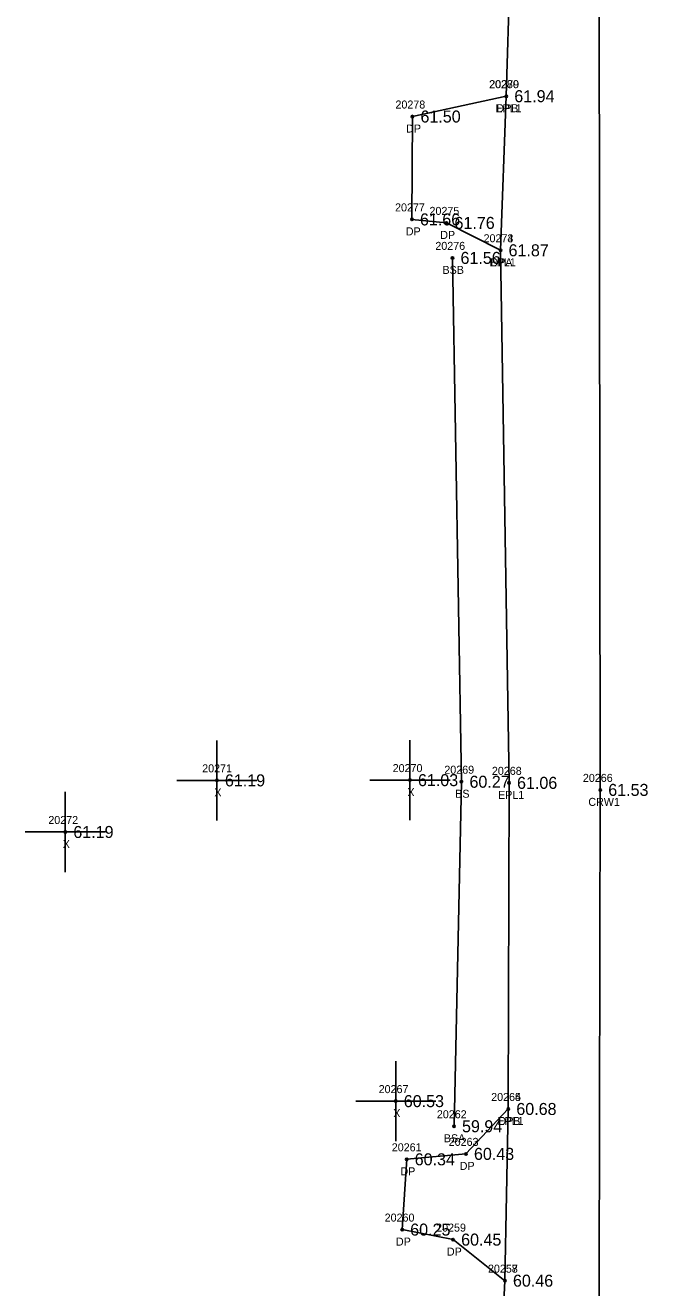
# Model space of a CAD drawing. Extents: x 2420351 to 2422725, y 845330 to 846558.
# Drawn here: x 2420888.2 to 2420966, y 845834.4 to 845992.1 of the extents above; entities that cross this region are included whole.
import ezdxf

# ---------------------------------------------------------------- set-up
doc = ezdxf.new("R2010")
doc.units = 0
for name, color, linetype in [('RD_DTM_BkLn1', 7, 'Continuous'), ('RD_DTM_BkLn2', 7, 'Continuous'), ('RD_DTM_BkLn_txCode', 7, 'Continuous'), ('RD_EX_Driveway', 7, 'Continuous'), ('RD_EX_Driveway_txCode', 7, 'Continuous'), ('RD_EX_Misc', 7, 'Continuous'), ('RD_EX_Misc_txCode', 7, 'Continuous'), ('RD_EX_Road', 7, 'Continuous'), ('RD_EX_Road_txCode', 7, 'Continuous'), ('RD_EX_TX_Driveway_ELEV', 7, 'Continuous'), ('RD_EX_TX_Misc_ELEV', 7, 'Continuous'), ('RD_EX_TX_Road_ELEV', 7, 'Continuous'), ('RD_HC_Survey_ELEV', 7, 'Continuous'), ('RD_HC_Survey_txCode', 7, 'Continuous'), ('RD_SMD_Locator', 7, 'Continuous')]:
    doc.layers.add(name, color=color, linetype=linetype)

msp = doc.modelspace()

# ---------------------------------------------------------------- linework, layer by layer
at = {"layer": 'RD_DTM_BkLn1'}
msp.add_lwpolyline([(2420953.84, 845715.4), (2420955.91, 845728.49), (2420958.05, 845746.39), (2420959.33, 845767.92), (2420959.83, 845794.17), (2420960.04, 845896.62), (2420959.9, 845997.98), (2420960.79, 846105.06), (2420961.13, 846198.92)], dxfattribs=at)
at = {"layer": 'RD_DTM_BkLn2'}
msp.add_lwpolyline([(2420941.78, 845854.6), (2420942.71, 845897.64), (2420941.59, 845963.08)], dxfattribs=at)
at = {"layer": 'RD_EX_Driveway'}
for points in [[(2420947.59, 845964.03), (2420940.84, 845967.45), (2420936.53, 845967.89), (2420936.59, 845980.74), (2420948.31, 845983.28)], [(2420948.14, 845835.31), (2420941.67, 845840.44), (2420935.31, 845841.69), (2420935.87, 845850.47), (2420943.27, 845851.15), (2420948.56, 845856.76)]]:
    msp.add_lwpolyline(points, dxfattribs=at)
at = {"layer": 'RD_EX_Misc'}
for p, q in [((2420912.18, 845892.81), (2420912.18, 845902.81)), ((2420936.28, 845892.84), (2420936.28, 845902.84)), ((2420907.18, 845897.81), (2420917.18, 845897.81)), ((2420931.28, 845897.84), (2420941.28, 845897.84)), ((2420893.25, 845886.36), (2420893.25, 845896.36)), ((2420888.25, 845891.36), (2420898.25, 845891.36)), ((2420934.51, 845852.74), (2420934.51, 845862.74)), ((2420929.51, 845857.74), (2420939.51, 845857.74))]:
    msp.add_line(p, q, dxfattribs=at)
at = {"layer": 'RD_EX_Road'}
msp.add_lwpolyline([(2420911.08, 845716.87), (2420926.22, 845723.04), (2420936.01, 845731.06), (2420942.67, 845742.11), (2420946.54, 845756.04), (2420945.56, 845775.49), (2420946.2, 845794.55), (2420948.14, 845835.31), (2420948.56, 845856.76), (2420948.65, 845897.5), (2420947.59, 845964.03), (2420948.31, 845983.28), (2420948.75, 845998.25), (2420949.7, 846105.56), (2420949.53, 846120.86), (2420949.28, 846141.3), (2420949.41, 846199.43)], dxfattribs=at)
at = {"layer": 'RD_SMD_Locator'}
for centre in [(2420948.31, 845983.28), (2420948.31, 845983.28), (2420936.59, 845980.74), (2420936.53, 845967.89), (2420940.84, 845967.45), (2420947.59, 845964.03), (2420947.59, 845964.03), (2420941.59, 845963.08), (2420912.18, 845897.81), (2420936.28, 845897.84), (2420942.71, 845897.64), (2420948.65, 845897.5), (2420960.04, 845896.62), (2420893.25, 845891.36), (2420934.51, 845857.74), (2420948.56, 845856.76), (2420948.56, 845856.76), (2420941.78, 845854.6), (2420935.87, 845850.47), (2420943.27, 845851.15), (2420935.31, 845841.69), (2420941.67, 845840.44), (2420948.14, 845835.31), (2420948.14, 845835.31)]:
    msp.add_circle(centre, 0.15, dxfattribs=at)

# ---------------------------------------------------------------- texts
at = {"layer": 'RD_DTM_BkLn_txCode'}
for s, p in [('20276', (2420939.45, 845964.08)), ('BSB', (2420940.34, 845961.08)), ('20269', (2420940.57, 845898.64)), ('BS', (2420941.93, 845895.64)), ('20262', (2420939.64, 845855.6)), ('BSA', (2420940.51, 845852.6))]:
    msp.add_text(s, height=1, dxfattribs=at).set_placement(p)
at = {"layer": 'RD_EX_Driveway_txCode'}
for s, p in [('20279', (2420946.19, 845984.28)), ('20278', (2420934.47, 845981.74)), ('DPB', (2420947.06, 845981.28)), ('DP', (2420935.81, 845978.74)), ('20277', (2420934.42, 845968.89)), ('20275', (2420938.72, 845968.45)), ('DP', (2420935.76, 845965.89)), ('DP', (2420940.06, 845965.45)), ('20274', (2420945.47, 845965.03)), ('DPA', (2420946.32, 845962.03)), ('20264', (2420946.42, 845857.76)), ('DPB', (2420947.31, 845854.76)), ('20261', (2420934.01, 845851.47)), ('20263', (2420941.12, 845852.15)), ('DP', (2420942.49, 845849.15)), ('DP', (2420935.09, 845848.47)), ('20260', (2420933.12, 845842.69)), ('20259', (2420939.55, 845841.44)), ('DP', (2420934.53, 845839.69)), ('DP', (2420940.89, 845838.44)), ('20258', (2420946.02, 845836.31))]:
    msp.add_text(s, height=1, dxfattribs=at).set_placement(p)
at = {"layer": 'RD_EX_Misc_txCode'}
for s, p in [('20271', (2420910.34, 845898.81)), ('20270', (2420934.12, 845898.84)), ('X', (2420911.86, 845895.81)), ('X', (2420935.96, 845895.84)), ('20272', (2420891.13, 845892.36)), ('X', (2420892.93, 845889.36)), ('20267', (2420932.37, 845858.74)), ('X', (2420934.2, 845855.74))]:
    msp.add_text(s, height=1, dxfattribs=at).set_placement(p)
at = {"layer": 'RD_EX_Road_txCode'}
for s, p in [('20280', (2420946.15, 845984.28)), ('EPL1', (2420946.94, 845981.28)), ('20273', (2420945.47, 845965.03)), ('EPL1', (2420946.22, 845962.03)), ('20268', (2420946.51, 845898.5)), ('EPL1', (2420947.28, 845895.5)), ('20265', (2420946.42, 845857.76)), ('EPL1', (2420947.19, 845854.76)), ('20257', (2420946.02, 845836.31))]:
    msp.add_text(s, height=1, dxfattribs=at).set_placement(p)
at = {"layer": 'RD_EX_TX_Driveway_ELEV'}
for s, p in [('61.94', (2420949.31, 845982.53)), ('61.50', (2420937.59, 845979.99)), ('61.66', (2420937.53, 845967.14)), ('61.76', (2420941.84, 845966.7)), ('61.87', (2420948.59, 845963.28)), ('60.68', (2420949.56, 845856.01)), ('60.43', (2420944.27, 845850.4)), ('60.34', (2420936.87, 845849.72)), ('60.25', (2420936.31, 845840.94)), ('60.45', (2420942.67, 845839.69)), ('60.46', (2420949.14, 845834.56))]:
    msp.add_text(s, height=1.5, dxfattribs=at).set_placement(p)
at = {"layer": 'RD_EX_TX_Misc_ELEV'}
for s, p in [('61.56', (2420942.59, 845962.33)), ('61.19', (2420913.18, 845897.06)), ('61.03', (2420937.28, 845897.09)), ('60.27', (2420943.71, 845896.89)), ('61.19', (2420894.25, 845890.61)), ('60.53', (2420935.51, 845856.99)), ('59.94', (2420942.78, 845853.85))]:
    msp.add_text(s, height=1.5, dxfattribs=at).set_placement(p)
at = {"layer": 'RD_EX_TX_Road_ELEV'}
for s, p in [('61.94', (2420949.31, 845982.53)), ('61.87', (2420948.59, 845963.28)), ('61.06', (2420949.65, 845896.75)), ('60.68', (2420949.56, 845856.01)), ('60.46', (2420949.14, 845834.56))]:
    msp.add_text(s, height=1.5, dxfattribs=at).set_placement(p)
at = {"layer": 'RD_HC_Survey_ELEV'}
msp.add_text('61.53', height=1.5, dxfattribs=at).set_placement((2420961.04, 845895.87))
at = {"layer": 'RD_HC_Survey_txCode'}
for s, p in [('20266', (2420957.87, 845897.62)), ('CRW1', (2420958.55, 845894.62))]:
    msp.add_text(s, height=1, dxfattribs=at).set_placement(p)

doc.saveas('drawing.dxf')
